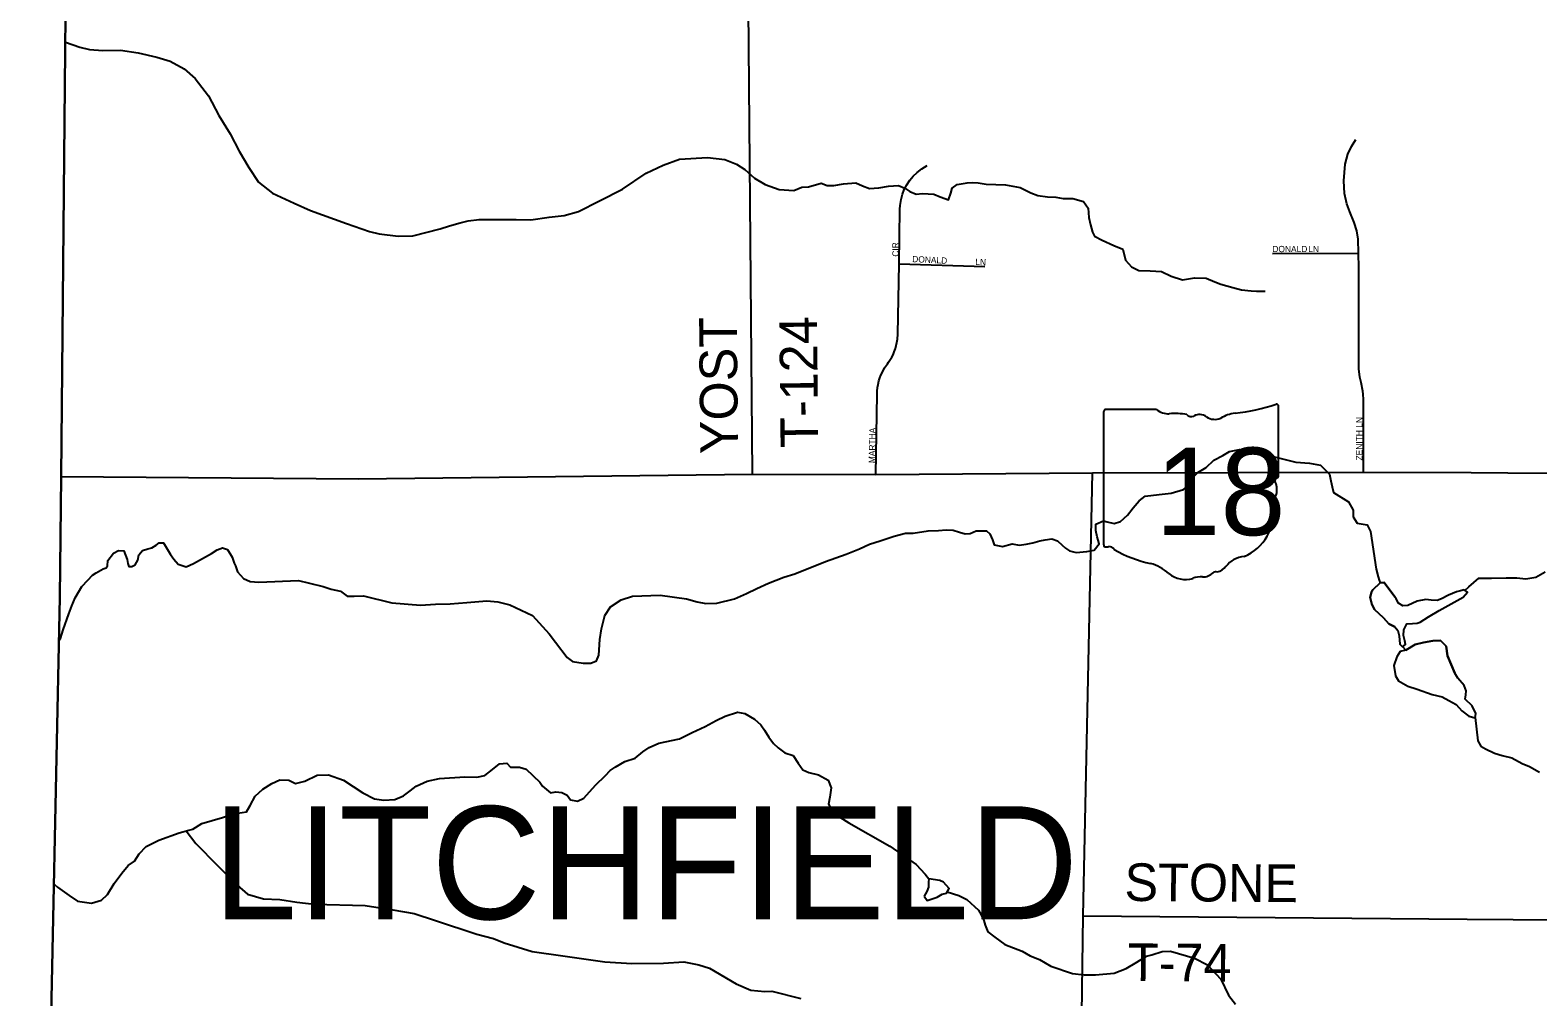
# Model space of a CAD drawing. Extents: x 1985906 to 2277390, y 930619 to 1324581.
# Drawn here: x 2085773 to 2097777, y 1150219 to 1157918 of the extents above; entities that cross this region are included whole.
import ezdxf

# ---------------------------------------------------------------- set-up
doc = ezdxf.new("R2010")
doc.units = 0
for name, color, linetype in [('GM_X_Adjacent_County', 7, 'Continuous'), ('GM_X_County', 7, 'Continuous'), ('GM_X_County_Road', 7, 'Continuous'), ('GM_X_Minor_River', 7, 'Continuous'), ('GM_X_State_Location', 7, 'Continuous'), ('GM_X_State_Route', 7, 'Continuous'), ('GM_X_State_Shield', 7, 'Continuous'), ('GM_X_Township', 7, 'Continuous'), ('GM_X_Township_Road', 7, 'Continuous'), ('GM_X_Township_Road_Text', 7, 'Continuous'), ('GM_X_Township_Subdivision', 7, 'Continuous'), ('GM_X_Township_Subdivision_Text', 7, 'Continuous'), ('GM_X_Township_Text', 7, 'Continuous')]:
    doc.layers.add(name, color=color, linetype=linetype)

msp = doc.modelspace()

# ---------------------------------------------------------------- linework, layer by layer
at = {"layer": 'GM_X_Adjacent_County'}
msp.add_lwpolyline([(2113358, 1166008), (2106159, 1165987), (2105360, 1165986), (2099554, 1165974), (2091388, 1165958), (2088816, 1165953), (2086130, 1165948), (2086087, 1161432), (2086019, 1154363), (2086010, 1153403), (2085923, 1149181), (2085904, 1148231), (2085903, 1148166), (2085793, 1142829), (2081417, 1142846), (2072419, 1142880), (2061930, 1142920), (2059427, 1142930), (2059330, 1135139), (2059259, 1129509), (2059186, 1123686), (2059120, 1118390)], dxfattribs=at)
at = {"layer": 'GM_X_County'}
msp.add_lwpolyline([(2113358, 1166008), (2106159, 1165987), (2105360, 1165986), (2099554, 1165974), (2091388, 1165958), (2088816, 1165953), (2086130, 1165948), (2086087, 1161432), (2086019, 1154363), (2086010, 1153403), (2085923, 1149181), (2085904, 1148231), (2085903, 1148166), (2085793, 1142829), (2081417, 1142846), (2072419, 1142880), (2061930, 1142920), (2059427, 1142930), (2059330, 1135139), (2059259, 1129509), (2059186, 1123686), (2059120, 1118390)], dxfattribs=at)
at = {"layer": 'GM_X_County_Road'}
msp.add_lwpolyline([(2094120, 1148116), (2094157, 1150863), (2094230, 1154392)], dxfattribs=at)
at = {"layer": 'GM_X_Minor_River'}
for points in [[(2086056, 1157823), (2086168, 1157784), (2086245, 1157765), (2086351, 1157757), (2086492, 1157758), (2086634, 1157738), (2086783, 1157702), (2086888, 1157670), (2086999, 1157609), (2087087, 1157534), (2087193, 1157395), (2087275, 1157239), (2087366, 1157092), (2087438, 1156955), (2087514, 1156825), (2087592, 1156708), (2087702, 1156621), (2087875, 1156539), (2088004, 1156483), (2088291, 1156378), (2088474, 1156315), (2088552, 1156296), (2088703, 1156278), (2088821, 1156281), (2089037, 1156336), (2089111, 1156361), (2089197, 1156383), (2089261, 1156400), (2089347, 1156411), (2089495, 1156411), (2089642, 1156409), (2089760, 1156408), (2089906, 1156428), (2090026, 1156442), (2090140, 1156474), (2090307, 1156560), (2090488, 1156651), (2090677, 1156778), (2090812, 1156842), (2090944, 1156890), (2091166, 1156905), (2091303, 1156889), (2091396, 1156852), (2091462, 1156809), (2091540, 1156740), (2091625, 1156689), (2091737, 1156648), (2091854, 1156642), (2091916, 1156667), (2091970, 1156669), (2092070, 1156699), (2092120, 1156680), (2092172, 1156680), (2092250, 1156693), (2092346, 1156701), (2092399, 1156677), (2092455, 1156656), (2092529, 1156663), (2092607, 1156676), (2092687, 1156681), (2092736, 1156660), (2092776, 1156634), (2092827, 1156613), (2092877, 1156618), (2092969, 1156613), (2093018, 1156590), (2093086, 1156568), (2093103, 1156619), (2093113, 1156661), (2093155, 1156688), (2093233, 1156701), (2093279, 1156705), (2093321, 1156702), (2093385, 1156691), (2093538, 1156687), (2093656, 1156666), (2093739, 1156623), (2093795, 1156600), (2093874, 1156591), (2093938, 1156588), (2093998, 1156577), (2094075, 1156578), (2094159, 1156553), (2094196, 1156501), (2094203, 1156425), (2094216, 1156367), (2094231, 1156309), (2094247, 1156277), (2094308, 1156246), (2094401, 1156203), (2094474, 1156174), (2094493, 1156086), (2094542, 1156034), (2094600, 1156005), (2094691, 1156000), (2094781, 1155996), (2094858, 1155960), (2094948, 1155930), (2095044, 1155945), (2095135, 1155944), (2095205, 1155913)], [(2095205, 1155913), (2095252, 1155896), (2095348, 1155869), (2095417, 1155850), (2095495, 1155841), (2095537, 1155839), (2095605, 1155840)], [(2093171, 1153920), (2093217, 1153907), (2093258, 1153908), (2093305, 1153930), (2093386, 1153931), (2093414, 1153906), (2093435, 1153860), (2093449, 1153818), (2093514, 1153805), (2093592, 1153826), (2093648, 1153815), (2093702, 1153823), (2093756, 1153836), (2093812, 1153851), (2093854, 1153860), (2093908, 1153866), (2093952, 1153851), (2093989, 1153815), (2094015, 1153792), (2094048, 1153772), (2094100, 1153757), (2094186, 1153766), (2094244, 1153777), (2094283, 1153827), (2094277, 1153857), (2094269, 1153883), (2094258, 1153933), (2094259, 1153984), (2094319, 1154010), (2094347, 1154001), (2094403, 1153990), (2094455, 1154006), (2094509, 1154055), (2094554, 1154114), (2094603, 1154169), (2094651, 1154206), (2094763, 1154219), (2094857, 1154231), (2094957, 1154260), (2094996, 1154291), (2095028, 1154353), (2095071, 1154396), (2095135, 1154435), (2095198, 1154494), (2095268, 1154531), (2095323, 1154562), (2095401, 1154577), (2095534, 1154553), (2095627, 1154532), (2095711, 1154513), (2095850, 1154477), (2095960, 1154470), (2096047, 1154454), (2096118, 1154382), (2096129, 1154328), (2096138, 1154282), (2096150, 1154236), (2096270, 1154162), (2096307, 1154094), (2096307, 1154042), (2096338, 1153992), (2096419, 1153977), (2096444, 1153925), (2096490, 1153625), (2096505, 1153563), (2096513, 1153537), (2096522, 1153515), (2096552, 1153519), (2096638, 1153406)], [(2086007, 1153063), (2086015, 1153074), (2086036, 1153142), (2086081, 1153269), (2086104, 1153334), (2086133, 1153396), (2086186, 1153486), (2086233, 1153538), (2086271, 1153577), (2086298, 1153597), (2086354, 1153628), (2086378, 1153637), (2086390, 1153651), (2086391, 1153693), (2086436, 1153752), (2086478, 1153775), (2086518, 1153771), (2086547, 1153701), (2086552, 1153669), (2086558, 1153647), (2086584, 1153646), (2086610, 1153660), (2086630, 1153698), (2086639, 1153739), (2086669, 1153773), (2086711, 1153788), (2086743, 1153796), (2086776, 1153815), (2086800, 1153835), (2086836, 1153834), (2086892, 1153742), (2086916, 1153704), (2086951, 1153665), (2087015, 1153645), (2087073, 1153670), (2087216, 1153751), (2087262, 1153779), (2087306, 1153794), (2087344, 1153782), (2087381, 1153721), (2087398, 1153673), (2087408, 1153651), (2087423, 1153605), (2087472, 1153551), (2087524, 1153528), (2087593, 1153521), (2087911, 1153535), (2087998, 1153514), (2088107, 1153486), (2088171, 1153467), (2088243, 1153451), (2088296, 1153410), (2088352, 1153411), (2088426, 1153412), (2088654, 1153357), (2088881, 1153338), (2089001, 1153347), (2089117, 1153349), (2089249, 1153359), (2089408, 1153373), (2089496, 1153364), (2089593, 1153340), (2089772, 1153256), (2089905, 1153109), (2089956, 1153043), (2090050, 1152922), (2090090, 1152891), (2090175, 1152876), (2090237, 1152877), (2090283, 1152895), (2090300, 1152940), (2090310, 1153066), (2090321, 1153151), (2090348, 1153256), (2090393, 1153324), (2090478, 1153380), (2090570, 1153411), (2090790, 1153418), (2090999, 1153389), (2091084, 1153364), (2091154, 1153353), (2091241, 1153354), (2091380, 1153390), (2091476, 1153432), (2091560, 1153471), (2091651, 1153514), (2091773, 1153562), (2091861, 1153589), (2092106, 1153685), (2092269, 1153744), (2092377, 1153787), (2092457, 1153824), (2092541, 1153852), (2092652, 1153889), (2092742, 1153913), (2092804, 1153911), (2092924, 1153931), (2093005, 1153934), (2093065, 1153939), (2093123, 1153936), (2093171, 1153920)], [(2097196, 1153456), (2097228, 1153484), (2097307, 1153554), (2097409, 1153553), (2097524, 1153555), (2097610, 1153556), (2097682, 1153547), (2097762, 1153562), (2097836, 1153603)], [(2096522, 1153515), (2096464, 1153460), (2096453, 1153444), (2096443, 1153399), (2096456, 1153347), (2096475, 1153303), (2096548, 1153238), (2096591, 1153189), (2096637, 1153167)], [(2096637, 1153167), (2096591, 1153189), (2096548, 1153238), (2096475, 1153303), (2096456, 1153347), (2096443, 1153399), (2096453, 1153444), (2096464, 1153460), (2096522, 1153515)], [(2096638, 1153406), (2096552, 1153519), (2096522, 1153515)], [(2096637, 1153167), (2096662, 1153137), (2096672, 1153095), (2096679, 1153029), (2096700, 1153007), (2096723, 1153024), (2096717, 1153054), (2096706, 1153098), (2096710, 1153142), (2096735, 1153191), (2096779, 1153193), (2096815, 1153196), (2096839, 1153204), (2096905, 1153245), (2096990, 1153296), (2097181, 1153403), (2097217, 1153442), (2097190, 1153460), (2097160, 1153453), (2097130, 1153445), (2097065, 1153418), (2097011, 1153389), (2096975, 1153376), (2096927, 1153378), (2096885, 1153383), (2096817, 1153370), (2096743, 1153337), (2096703, 1153333), (2096668, 1153354), (2096650, 1153388), (2096638, 1153406)], [(2096697, 1153011), (2096726, 1152980), (2096800, 1153025), (2096866, 1153040), (2096940, 1153055), (2097002, 1153058), (2097048, 1153012), (2097058, 1152934), (2097116, 1152796)], [(2097116, 1152796), (2097058, 1152934), (2097048, 1153012), (2097002, 1153058), (2096940, 1153055), (2096866, 1153040), (2096800, 1153025), (2096725, 1152980)], [(2096725, 1152980), (2096680, 1152969), (2096653, 1152926), (2096630, 1152858), (2096643, 1152776), (2096668, 1152736), (2096742, 1152693), (2096815, 1152670), (2096936, 1152627), (2097014, 1152608), (2097069, 1152579), (2097126, 1152546), (2097172, 1152496), (2097227, 1152455), (2097277, 1152441), (2097283, 1152476), (2097254, 1152537), (2097199, 1152591), (2097203, 1152625), (2097206, 1152655), (2097191, 1152699), (2097140, 1152757), (2097116, 1152796)], [(2085967, 1151114), (2085990, 1151092), (2086084, 1151025), (2086150, 1150982), (2086263, 1150964), (2086341, 1150989), (2086390, 1151034), (2086443, 1151121), (2086504, 1151204), (2086555, 1151265), (2086603, 1151300), (2086642, 1151358), (2086697, 1151417), (2086797, 1151467), (2086960, 1151525), (2087038, 1151546), (2087068, 1151555), (2087140, 1151600), (2087304, 1151646), (2087393, 1151676), (2087495, 1151693), (2087525, 1151742), (2087566, 1151818), (2087625, 1151872), (2087697, 1151919), (2087762, 1151946), (2087832, 1151945), (2087885, 1151917), (2087959, 1151938), (2088058, 1151984), (2088149, 1151987), (2088268, 1151945), (2088421, 1151844), (2088516, 1151797), (2088589, 1151786), (2088677, 1151790), (2088747, 1151821), (2088798, 1151860), (2088846, 1151898), (2088935, 1151936), (2089033, 1151959), (2089234, 1151972), (2089330, 1151969), (2089394, 1151982), (2089455, 1152029), (2089509, 1152074), (2089569, 1152081), (2089597, 1152049), (2089670, 1152048), (2089722, 1152033), (2089830, 1151928), (2089852, 1151898), (2089915, 1151845), (2089959, 1151853), (2090007, 1151846), (2090048, 1151824), (2090076, 1151789), (2090131, 1151777), (2090181, 1151800), (2090275, 1151904), (2090354, 1151983), (2090390, 1152022), (2090432, 1152048), (2090509, 1152094), (2090589, 1152121), (2090650, 1152170), (2090702, 1152205), (2090778, 1152240), (2090942, 1152274), (2091045, 1152324), (2091147, 1152371), (2091234, 1152419), (2091306, 1152454), (2091404, 1152485), (2091464, 1152476), (2091541, 1152431), (2091590, 1152386), (2091620, 1152344), (2091655, 1152288), (2091692, 1152238), (2091729, 1152203), (2091783, 1152163), (2091848, 1152142), (2091889, 1152081), (2091926, 1152027), (2091974, 1152007), (2092051, 1151988), (2092127, 1151945), (2092150, 1151883), (2092139, 1151809), (2092130, 1151753), (2092169, 1151683), (2092291, 1151606), (2092618, 1151418), (2092827, 1151273), (2092900, 1151197), (2092929, 1151160), (2092925, 1151133), (2092926, 1151093), (2092912, 1151057), (2092891, 1151021)], [(2097278, 1152444), (2097300, 1152257), (2097323, 1152215), (2097361, 1152194), (2097432, 1152160), (2097492, 1152141), (2097569, 1152122), (2097652, 1152077), (2097710, 1152054), (2097791, 1152009)], [(2087015, 1151540), (2087092, 1151441), (2087265, 1151264), (2087422, 1151108), (2087505, 1151037), (2087630, 1151000), (2087760, 1150994), (2087897, 1150972), (2088035, 1150958), (2088441, 1150947), (2088660, 1150912), (2088831, 1150884), (2089000, 1150827), (2089330, 1150717), (2089463, 1150684), (2089548, 1150649), (2089771, 1150580), (2090013, 1150545), (2090348, 1150498), (2090563, 1150485), (2090817, 1150486), (2090978, 1150497), (2091098, 1150474), (2091181, 1150447), (2091393, 1150322), (2091512, 1150273), (2091623, 1150261), (2091677, 1150265), (2091908, 1150206)], [(2092891, 1151021), (2092916, 1150985), (2092995, 1151014), (2093035, 1151037), (2093069, 1151045), (2093091, 1151081), (2093046, 1151131), (2093015, 1151145), (2092928, 1151160)], [(2093075, 1151055), (2093168, 1151026), (2093232, 1150995), (2093324, 1150910), (2093344, 1150872), (2093365, 1150826), (2093376, 1150790), (2093398, 1150738), (2093453, 1150693), (2093532, 1150636), (2093671, 1150582), (2093734, 1150546), (2093809, 1150517), (2093900, 1150462), (2094073, 1150406), (2094165, 1150394), (2094256, 1150393), (2094404, 1150407), (2094498, 1150444), (2094585, 1150494), (2094660, 1150543), (2094704, 1150554), (2094786, 1150581), (2094852, 1150584), (2095044, 1150528), (2095147, 1150473), (2095253, 1150360), (2095315, 1150231), (2095370, 1150161)]]:
    msp.add_lwpolyline(points, dxfattribs=at)
at = {"layer": 'GM_X_State_Route'}
for points in [[(2086019, 1154363), (2088388, 1154345), (2091525, 1154382), (2092505, 1154379), (2094230, 1154392), (2096390, 1154399), (2097247, 1154394)], [(2097247, 1154394), (2097537, 1154392), (2098729, 1154386)]]:
    msp.add_lwpolyline(points, dxfattribs=at)
at = {"layer": 'GM_X_State_Shield'}
for p, q in [((2094320, 1154878), (2094320, 1153821)), ((2094741, 1154896), (2094333, 1154896)), ((2095712, 1154369), (2095712, 1154922)), ((2095712, 1154369), (2095712, 1154369))]:
    msp.add_line(p, q, dxfattribs=at)
for centre, radius, start, end in [((2094336, 1154880), 16.1, 98.1301, 188.1301), ((2094838, 1155019), 156, 231.6195, 271.1119), ((2094890, 1154303), 562, 80.4867, 94.9883), ((2095017, 1154885), 45.1, 219.7921, 297.1024), ((2095084, 1154763), 93.8, 54.4667, 119.1411), ((2095404, 1154573), 297, 97.3462, 120.7689), ((2095216, 1156336), 1476, 275.8445, 288.9065), ((2095696, 1154924), 15.5, 351.8621, 97.738), ((2095205, 1154931), 113, 233.8562, 294.8282), ((2095708, 1154329), 24, 107.944, 210.337), ((2095556, 1154259), 144, 340.033, 23.6496), ((2095695, 1154367), 16.6, 289.6038, 7.7341), ((2095767, 1154138), 105, 136.8065, 186.9296), ((2095299, 1154068), 369, 292.3089, 8.9858), ((2094336, 1153819), 16.3, 171.9584, 258.3066), ((2094338, 1153927), 124, 267.339, 280.6039), ((2094364, 1153760), 44.8, 29.7484, 93.2717), ((2094929, 1154709), 1066, 240.4129, 257.1985), ((2094611, 1153346), 334, 47.1842, 75.836), ((2095454, 1153524), 202, 94.4031, 142.5768), ((2094972, 1153755), 212, 230.7004, 286.2918), ((2095094, 1153390), 174, 85.6951, 111.2099), ((2095110, 1153676), 113, 268.777, 315.5493), ((2095212, 1153573), 31.8, 65.7517, 132.6484), ((2095198, 1153719), 119, 282.8732, 323.2771)]:
    msp.add_arc(centre, radius, start, end, dxfattribs=at)
at = {"layer": 'GM_X_Township'}
msp.add_lwpolyline([(2113092, 1142777), (2105809, 1142742), (2105186, 1142765), (2099759, 1142765), (2094059, 1142740), (2091371, 1142782), (2085793, 1142829), (2085903, 1148166), (2085904, 1148231), (2085923, 1149181), (2086010, 1153403), (2086019, 1154363), (2086087, 1161432), (2086130, 1165948), (2088816, 1165953), (2091388, 1165958), (2099554, 1165974), (2105360, 1165986), (2106159, 1165987), (2113358, 1166008)], dxfattribs=at)
at = {"layer": 'GM_X_Township_Road'}
for points in [[(2091525, 1154382), (2091471, 1160575)], [(2097214, 1150838), (2097946, 1150832), (2099009, 1150808), (2099379, 1150806), (2099474, 1150811), (2099592, 1150841), (2099827, 1150934)], [(2094157, 1150863), (2097214, 1150838)]]:
    msp.add_lwpolyline(points, dxfattribs=at)
at = {"layer": 'GM_X_Township_Subdivision'}
for points in [[(2096390, 1154399), (2096389, 1154977), (2096387, 1155018), (2096384, 1155044), (2096370, 1155111), (2096360, 1155155), (2096352, 1155220), (2096352, 1155321), (2096351, 1155638), (2096351, 1156025), (2096350, 1156141), (2096347, 1156253), (2096336, 1156320), (2096315, 1156385), (2096280, 1156470), (2096255, 1156536), (2096237, 1156617), (2096233, 1156718), (2096243, 1156852), (2096265, 1156931), (2096292, 1156991), (2096327, 1157047)], [(2092505, 1154379), (2092516, 1155020), (2092517, 1155042), (2092520, 1155072), (2092524, 1155097), (2092531, 1155125), (2092538, 1155149), (2092547, 1155171), (2092558, 1155195), (2092576, 1155228), (2092599, 1155261), (2092608, 1155274), (2092623, 1155297), (2092633, 1155314), (2092643, 1155333), (2092653, 1155356), (2092662, 1155382), (2092669, 1155407), (2092674, 1155430), (2092678, 1155456), (2092681, 1155498), (2092691, 1156057), (2092698, 1156492), (2092700, 1156522), (2092708, 1156570), (2092719, 1156611), (2092733, 1156648), (2092754, 1156687), (2092778, 1156724), (2092804, 1156755), (2092834, 1156784), (2092873, 1156815), (2092916, 1156840)], [(2092691, 1156057), (2093375, 1156035)], [(2095665, 1156140), (2096350, 1156141)]]:
    msp.add_lwpolyline(points, dxfattribs=at)

# ---------------------------------------------------------------- texts
at = {"layer": 'GM_X_State_Location'}
for s in ['s', 'r']:
    msp.add_text(s, height=1, dxfattribs=at).set_placement((2095000, 1154279))
msp.add_text('18', height=1, rotation=0, dxfattribs=at).set_placement((2094748, 1154206))
at = {"layer": 'GM_X_State_Shield'}
msp.add_text('18', height=696.1, dxfattribs=at).set_placement((2094732, 1153896))
at = {"layer": 'GM_X_Township_Road_Text'}
for s, rotation, p in [('YOST', 90.5254, (2091409, 1154543)), ('T-124', 90.5614, (2092048, 1154593)), ('STONE', 359.5743, (2094485, 1150983)), ('T-74', 359.6465, (2094512, 1150345))]:
    msp.add_text(s, height=300, rotation=rotation, dxfattribs=at).set_placement(p)
at = {"layer": 'GM_X_Township_Subdivision_Text'}
for s, rotation, p in [('CIR', 90, (2092688, 1156114)), ('DONALD', 0, (2095663, 1156150)), ('LN', 0, (2095949, 1156150)), ('DONALD', 357.0908, (2092795, 1156071)), ('LN', 356.8219, (2093297, 1156049)), ('MARTHA', 89.0457, (2092499, 1154469)), ('ZENITH LN', 90, (2096380, 1154491))]:
    msp.add_text(s, height=50, rotation=rotation, dxfattribs=at).set_placement(p)
at = {"layer": 'GM_X_Township_Text'}
msp.add_text('LITCHFIELD', height=900, rotation=0, dxfattribs=at).set_placement((2087229, 1150837))

doc.saveas('drawing.dxf')
